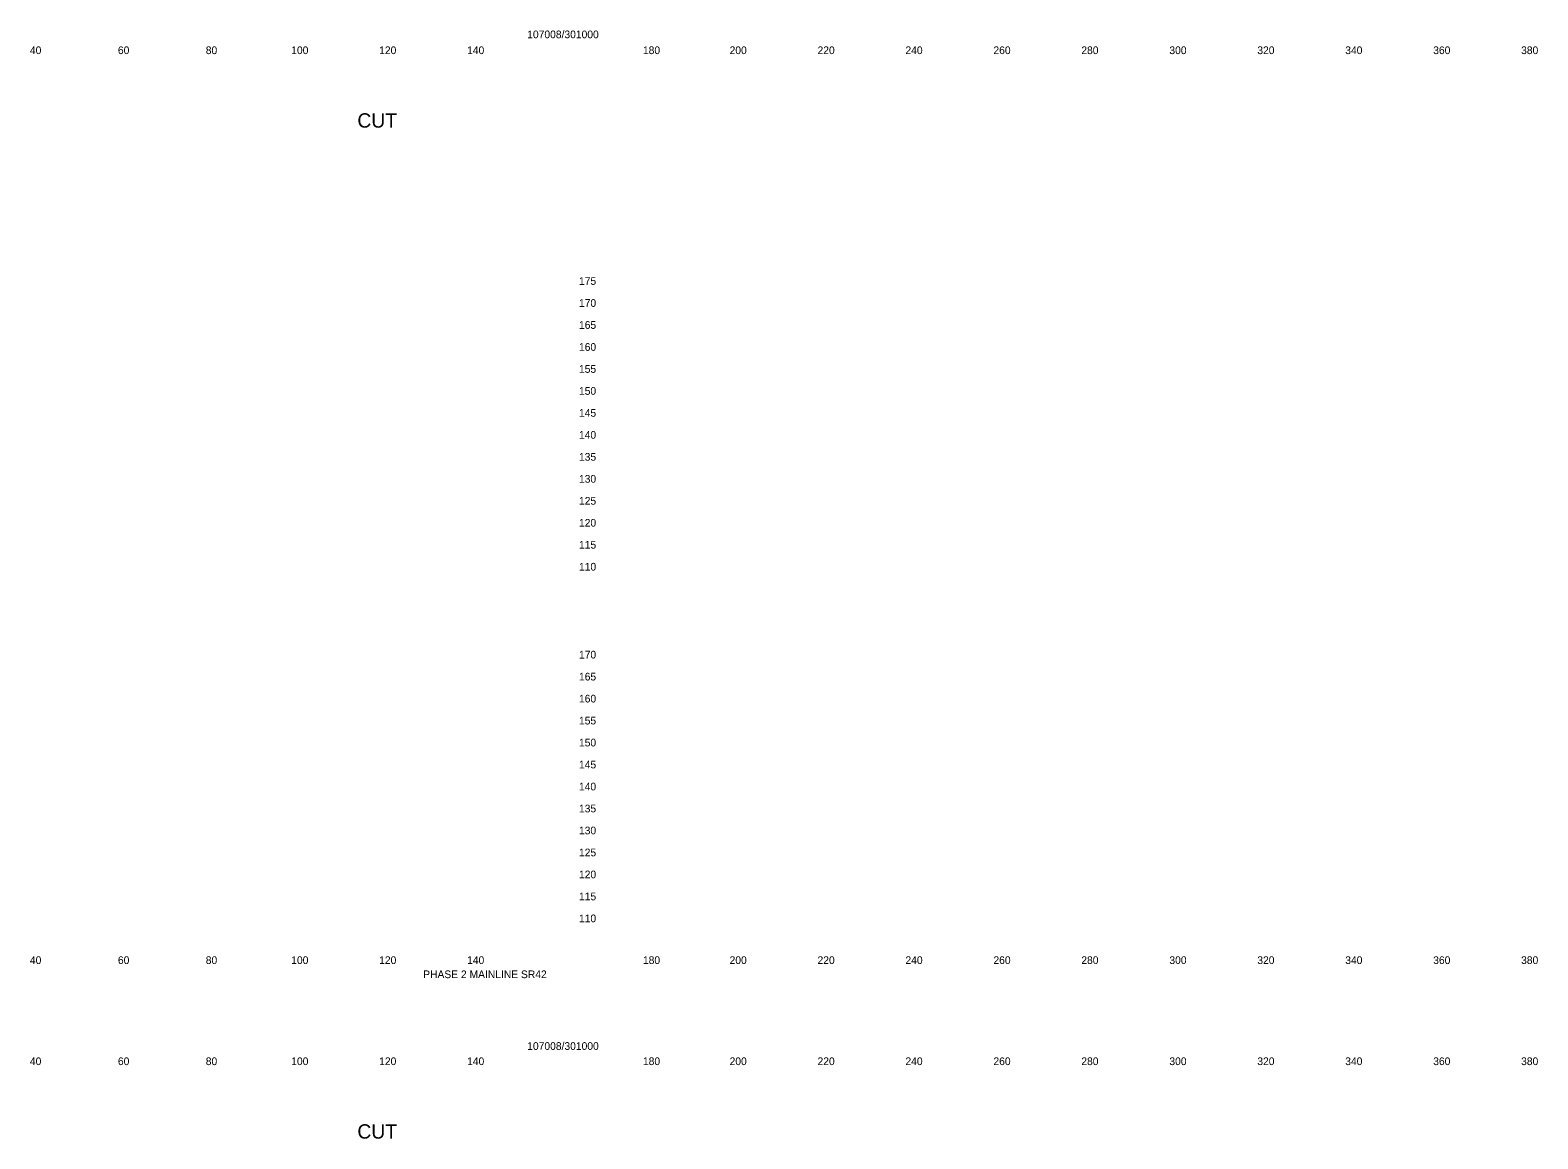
# Model space of a CAD drawing. Extents: x 21281 to 22024, y 6472 to 15208.
# Drawn here: x 21681.3 to 22024.2, y 10575.6 to 10827.8 of the extents above; entities that cross this region are included whole.
import ezdxf

# ---------------------------------------------------------------- set-up
doc = ezdxf.new("R2010")
doc.units = 0
doc.layers.add('XS_SHEET_LABELS_ELEVATION', color=7, linetype='Continuous')
doc.layers.add('XS_SHEET_LABELS_OFFSET', color=7, linetype='Continuous')

msp = doc.modelspace()

# ---------------------------------------------------------------- texts
at = {"layer": 'XS_SHEET_LABELS_ELEVATION'}
for s, p in [('  175  ', (21804.84, 10769.84)), ('  170  ', (21804.84, 10764.84)), ('  165  ', (21804.84, 10759.84)), ('  160  ', (21804.84, 10754.84)), ('  155  ', (21804.84, 10749.84)), ('  150  ', (21804.84, 10744.84)), ('  145  ', (21804.84, 10739.84)), ('  140  ', (21804.84, 10734.84)), ('  135  ', (21804.84, 10729.84)), ('  130  ', (21804.84, 10724.84)), ('  125  ', (21804.84, 10719.84)), ('  120  ', (21804.84, 10714.84)), ('  115  ', (21804.84, 10709.84)), ('  110  ', (21804.84, 10704.84)), ('  170  ', (21804.84, 10684.84)), ('  165  ', (21804.84, 10679.84)), ('  160  ', (21804.84, 10674.84)), ('  155  ', (21804.84, 10669.84)), ('  150  ', (21804.84, 10664.84)), ('  145  ', (21804.84, 10659.84)), ('  140  ', (21804.84, 10654.84)), ('  135  ', (21804.84, 10649.84)), ('  130  ', (21804.84, 10644.84)), ('  125  ', (21804.84, 10639.84)), ('  120  ', (21804.84, 10634.84)), ('  115  ', (21804.84, 10629.84)), ('  110  ', (21804.84, 10624.84))]:
    msp.add_text(s, height=1.75, dxfattribs=at).set_placement(p)
at = {"layer": 'XS_SHEET_LABELS_OFFSET'}
for s, height, p in [('107008/301000', 1.75, (21794.37, 10825.95)), ('  40  ', 1.75, (21679.95, 10822.34)), ('  60  ', 1.75, (21699.97, 10822.34)), ('  80  ', 1.75, (21719.95, 10822.34)), ('  100  ', 1.75, (21739.39, 10822.34)), ('  120  ', 1.75, (21759.39, 10822.34)), ('  140  ', 1.75, (21779.39, 10822.34)), ('  180  ', 1.75, (21819.39, 10822.34)), ('  200  ', 1.75, (21839.1, 10822.34)), ('  220  ', 1.75, (21859.1, 10822.34)), ('  240  ', 1.75, (21879.1, 10822.34)), ('  260  ', 1.75, (21899.11, 10822.34)), ('  280  ', 1.75, (21919.1, 10822.34)), ('  300  ', 1.75, (21939.13, 10822.34)), ('  320  ', 1.75, (21959.13, 10822.34)), ('  340  ', 1.75, (21979.13, 10822.34)), ('  360  ', 1.75, (21999.14, 10822.34)), ('  380  ', 1.75, (22019.13, 10822.34)), ('CUT', 3.273, (21755.74, 10805.61)), ('  40  ', 1.75, (21679.95, 10615.34)), ('  60  ', 1.75, (21699.97, 10615.34)), ('  80  ', 1.75, (21719.95, 10615.34)), ('  100  ', 1.75, (21739.39, 10615.34)), ('  120  ', 1.75, (21759.39, 10615.34)), ('PHASE 2 MAINLINE SR42', 1.75, (21770.71, 10612.12)), ('  140  ', 1.75, (21779.39, 10615.34)), ('  180  ', 1.75, (21819.39, 10615.34)), ('  200  ', 1.75, (21839.1, 10615.34)), ('  220  ', 1.75, (21859.1, 10615.34)), ('  240  ', 1.75, (21879.1, 10615.34)), ('  260  ', 1.75, (21899.11, 10615.34)), ('  280  ', 1.75, (21919.1, 10615.34)), ('  300  ', 1.75, (21939.13, 10615.34)), ('  320  ', 1.75, (21959.13, 10615.34)), ('  340  ', 1.75, (21979.13, 10615.34)), ('  360  ', 1.75, (21999.14, 10615.34)), ('  380  ', 1.75, (22019.13, 10615.34)), ('107008/301000', 1.75, (21794.37, 10595.8)), ('  40  ', 1.75, (21679.95, 10592.34)), ('  60  ', 1.75, (21699.97, 10592.34)), ('  80  ', 1.75, (21719.95, 10592.34)), ('  100  ', 1.75, (21739.39, 10592.34)), ('  120  ', 1.75, (21759.39, 10592.34)), ('  140  ', 1.75, (21779.39, 10592.34)), ('  180  ', 1.75, (21819.39, 10592.34)), ('  200  ', 1.75, (21839.1, 10592.34)), ('  220  ', 1.75, (21859.1, 10592.34)), ('  240  ', 1.75, (21879.1, 10592.34)), ('  260  ', 1.75, (21899.11, 10592.34)), ('  280  ', 1.75, (21919.1, 10592.34)), ('  300  ', 1.75, (21939.13, 10592.34)), ('  320  ', 1.75, (21959.13, 10592.34)), ('  340  ', 1.75, (21979.13, 10592.34)), ('  360  ', 1.75, (21999.14, 10592.34)), ('  380  ', 1.75, (22019.13, 10592.34)), ('CUT', 3.273, (21755.74, 10575.61))]:
    msp.add_text(s, height=height, dxfattribs=at).set_placement(p)

doc.saveas('drawing.dxf')
